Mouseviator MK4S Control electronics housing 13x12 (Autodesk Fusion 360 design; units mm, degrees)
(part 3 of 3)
sketch "Sketch2" plane through (0, 0, 5) normal (0, 0, 1) x axis (-1, 0, 0)
  line L1 (-60.9644, -51.9879) -> (-20.9644, -51.9879)
  line L2 (-55.9644, -54.9879) -> (-60.9644, -51.9879)
  line L3 (-85.9644, -54.9879) -> (-55.9644, -54.9879)
  line L4 (-80.9644, -51.9879) -> (-85.9644, -54.9879)
  line L5 (-120.9644, -51.9879) -> (-80.9644, -51.9879)
  line L6 (-120.9644, -6.9879) -> (-120.9644, -51.9879)
  line L7 (-123.9644, -11.9879) -> (-120.9644, -6.9879)
  line L8 (-123.9644, 18.0121) -> (-123.9644, -11.9879)
  line L9 (-120.9644, 13.0121) -> (-123.9644, 18.0121)
  line L10 (-120.9644, 58.0121) -> (-120.9644, 13.0121)
  line L11 (-80.9644, 58.0121) -> (-120.9644, 58.0121)
  line L12 (-85.9644, 61.0121) -> (-80.9644, 58.0121)
  line L13 (-55.9644, 61.0121) -> (-85.9644, 61.0121)
  line L14 (-60.9644, 58.0121) -> (-55.9644, 61.0121)
  line L15 (-20.9644, 58.0121) -> (-60.9644, 58.0121)
  line L16 (-20.9644, 13.0121) -> (-20.9644, 58.0121)
  line L17 (-17.9644, 18.0121) -> (-20.9644, 13.0121)
  line L18 (-17.9644, -11.9879) -> (-17.9644, 18.0121)
  line L19 (-20.9644, -6.9879) -> (-17.9644, -11.9879)
  line L20 (-20.9644, -51.9879) -> (-20.9644, -6.9879)
  line L21 (-128.9644, 60.0121) -> (-122.9644, 60.0121)
  line L22 (-128.9644, 66.0121) -> (-128.9644, 60.0121)
  line L23 (-122.9644, 66.0121) -> (-128.9644, 66.0121)
  line L24 (-122.9644, 60.0121) -> (-122.9644, 66.0121)
  line L25 (-128.9644, -53.9879) -> (-128.9644, -59.9879)
  line L26 (-122.9644, -53.9879) -> (-128.9644, -53.9879)
  line L27 (-122.9644, -59.9879) -> (-122.9644, -53.9879)
  line L28 (-128.9644, -59.9879) -> (-122.9644, -59.9879)
  line L29 (-12.9644, -53.9879) -> (-18.9644, -53.9879)
  line L30 (-12.9644, -59.9879) -> (-12.9644, -53.9879)
  line L31 (-18.9644, -59.9879) -> (-12.9644, -59.9879)
  line L32 (-18.9644, -53.9879) -> (-18.9644, -59.9879)
  line L33 (-12.9644, 60.0121) -> (-12.9644, 66.0121)
  line L34 (-18.9644, 60.0121) -> (-12.9644, 60.0121)
  line L35 (-18.9644, 66.0121) -> (-18.9644, 60.0121)
  line L36 (-12.9644, 66.0121) -> (-18.9644, 66.0121)
  line L37 (-10.9644, -6.9879) -> (-10.9644, -61.9879)
  line L38 (-13.9644, -11.9879) -> (-10.9644, -6.9879)
  line L39 (-13.9644, 18.0121) -> (-13.9644, -11.9879)
  line L40 (-10.9644, 13.0121) -> (-13.9644, 18.0121)
  line L41 (-10.9644, 68.0121) -> (-10.9644, 13.0121)
  line L42 (-60.9644, 68.0121) -> (-10.9644, 68.0121)
  line L43 (-55.9644, 65.0121) -> (-60.9644, 68.0121)
  line L44 (-85.9644, 65.0121) -> (-55.9644, 65.0121)
  line L45 (-80.9644, 68.0121) -> (-85.9644, 65.0121)
  line L46 (-130.9644, 68.0121) -> (-80.9644, 68.0121)
  line L47 (-130.9644, 13.0121) -> (-130.9644, 68.0121)
  line L48 (-127.9644, 18.0121) -> (-130.9644, 13.0121)
  line L49 (-127.9644, -11.9879) -> (-127.9644, 18.0121)
  line L50 (-130.9644, -6.9879) -> (-127.9644, -11.9879)
  line L51 (-130.9644, -61.9879) -> (-130.9644, -6.9879)
  line L52 (-80.9644, -61.9879) -> (-130.9644, -61.9879)
  line L53 (-85.9644, -58.9879) -> (-80.9644, -61.9879)
  line L54 (-55.9644, -58.9879) -> (-85.9644, -58.9879)
  line L55 (-60.9644, -61.9879) -> (-55.9644, -58.9879)
  line L56 (-10.9644, -61.9879) -> (-60.9644, -61.9879)
  line L57 (-60.9644, -51.9879) -> (-20.9644, -51.9879)
  line L58 (-20.9644, -6.9879) -> (-20.9644, -51.9879)
  line L59 (-17.9644, -11.9879) -> (-17.9644, 3.0121)
  line L60 (-17.9644, 18.0121) -> (-17.9644, 3.0121)
  line L61 (-17.9644, 18.0121) -> (-20.9644, 13.0121)
  line L62 (-17.9644, -11.9879) -> (-20.9644, -6.9879)
  line L63 (-20.9644, 13.0121) -> (-20.9644, 58.0121)
  line L64 (-60.9644, 58.0121) -> (-20.9644, 58.0121)
  line L65 (-55.9644, 61.0121) -> (-70.9644, 61.0121)
  line L66 (-85.9644, 61.0121) -> (-70.9644, 61.0121)
  line L67 (-80.9644, 58.0121) -> (-85.9644, 61.0121)
  line L68 (-55.9644, 61.0121) -> (-60.9644, 58.0121)
  line L69 (-80.9644, 58.0121) -> (-120.9644, 58.0121)
  line L70 (-120.9644, 58.0121) -> (-120.9644, 13.0121)
  line L71 (-123.9644, 18.0121) -> (-123.9644, 3.0121)
  line L72 (-123.9644, 18.0121) -> (-120.9644, 13.0121)
  line L73 (-123.9644, -11.9879) -> (-123.9644, 3.0121)
  line L74 (-123.9644, -11.9879) -> (-120.9644, -6.9879)
  line L75 (-120.9644, -6.9879) -> (-120.9644, -51.9879)
  line L76 (-80.9644, -51.9879) -> (-120.9644, -51.9879)
  line L77 (-85.9644, -54.9879) -> (-70.9644, -54.9879)
  line L78 (-80.9644, -51.9879) -> (-85.9644, -54.9879)
  line L79 (-55.9644, -54.9879) -> (-60.9644, -51.9879)
  line L80 (-55.9644, -54.9879) -> (-70.9644, -54.9879)
  line L81 (-110.9144, -41.9379) -> (-31.0144, -41.9379)
  line L82 (-110.9144, 47.9621) -> (-110.9144, -41.9379)
  line L83 (-31.0144, 47.9621) -> (-110.9144, 47.9621)
  line L84 (-31.0144, -41.9379) -> (-31.0144, 47.9621)
  line L85 (-120.9144, -51.9379) -> (-80.7839, -51.9379)
  line L86 (-120.9144, -6.8074) -> (-120.9144, -51.9379)
  line L87 (-123.9144, -11.8074) -> (-120.9144, -6.8074)
  line L88 (-123.9144, 17.8316) -> (-123.9144, -11.8074)
  line L89 (-120.9144, 12.8316) -> (-123.9144, 17.8316)
  line L90 (-120.9144, 57.9621) -> (-120.9144, 12.8316)
  line L91 (-80.7839, 57.9621) -> (-120.9144, 57.9621)
  line L92 (-85.7839, 60.9621) -> (-80.7839, 57.9621)
  line L93 (-56.1449, 60.9621) -> (-85.7839, 60.9621)
  line L94 (-61.1449, 57.9621) -> (-56.1449, 60.9621)
  line L95 (-21.0144, 57.9621) -> (-61.1449, 57.9621)
  line L96 (-21.0144, 12.8316) -> (-21.0144, 57.9621)
  line L97 (-18.0144, 17.8316) -> (-21.0144, 12.8316)
  line L98 (-18.0144, -11.8074) -> (-18.0144, 17.8316)
  line L99 (-21.0144, -6.8074) -> (-18.0144, -11.8074)
  line L100 (-21.0144, -51.9379) -> (-21.0144, -6.8074)
  line L101 (-61.1449, -51.9379) -> (-21.0144, -51.9379)
  line L102 (-56.1449, -54.9379) -> (-61.1449, -51.9379)
  line L103 (-85.7839, -54.9379) -> (-56.1449, -54.9379)
  line L104 (-80.7839, -51.9379) -> (-85.7839, -54.9379)
  line L105 (-80.7839, 57.9621) -> (-61.1449, 57.9621)
  line L106 (-120.9144, 12.8316) -> (-120.9144, -6.8074)
  line L107 (-80.7839, -51.9379) -> (-61.1449, -51.9379)
  line L108 (-21.0144, 12.8316) -> (-21.0144, -6.8074)
  line L109 (-21.0144, -51.9379) -> (-120.9644, 58.0121)
  line L110 (-120.9644, -51.9879) -> (-20.9644, 58.0121)
  line L111 (-27.7672, 57.9621) -> (-27.7217, 58.0121)
  line L112 (-21.0144, 50.5241) -> (-20.9644, 50.5791)
  line L113 (-110.9144, -33.4999) -> (-36.8581, 47.9621)
  line L114 (-120.9644, -44.5549) -> (-120.9144, -44.4999)
  line L115 (-105.0708, -41.9379) -> (-31.0144, 39.5241)
  line L116 (-114.2071, -51.9879) -> (-114.1617, -51.9379)
  line L117 (-114.1618, 57.9621) -> (-114.2073, 58.0121)
  line L118 (-120.9144, 50.5239) -> (-120.9644, 50.5789)
  line L119 (-31.0144, -33.5042) -> (-105.0713, 47.9621)
  line L120 (-36.8621, -41.9379) -> (-110.9144, 39.5234)
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  point P79 (-120.9644, 58.0121)
  point P130 (-120.9644, 58.0121)
  point P73 (-20.9644, 58.0121)
  point P131 (-20.9644, 58.0121)
  point P85 (-120.9644, -51.9879)
  point P132 (-120.9644, -51.9879)
  point P133 (-27.7217, 58.0121)
  point P134 (-27.7672, 57.9621)
  point P135 (-36.8581, 47.9621)
  point P136 (-20.9644, 50.5791)
  point P137 (-21.0144, 50.5241)
  point P138 (-31.0144, 39.5241)
  point P139 (-110.9144, -33.4999)
  point P140 (-120.9144, -44.4999)
  point P141 (-120.9644, -44.5549)
  point P142 (-105.0708, -41.9379)
  point P143 (-114.1617, -51.9379)
  point P144 (-114.2071, -51.9879)
  point P145 (-114.2073, 58.0121)
  point P146 (-114.1618, 57.9621)
  point P147 (-105.0713, 47.9621)
  point P148 (-120.9644, 50.5789)
  point P149 (-120.9144, 50.5239)
  point P150 (-110.9144, 39.5234)
  point P151 (-31.0144, -33.5042)
  point P152 (-21.0144, -44.5047)
  point P153 (-36.8621, -41.9379)
  point P154 (-27.7716, -51.9379)
  point P155 (-20.9644, -44.5597)
  point P156 (-27.7261, -51.9879)
  horizontal L81
  vertical L82
  horizontal L83
  vertical L84
  coincident P79 P130
  coincident P73 P131
  coincident P85 P132
  coincident L15 P133
  coincident L95 P134
  coincident L83 P135
  collinear L111 L113
  coincident L16 P136
  coincident L96 P137
  coincident L84 P138
  collinear L112 L115
  coincident L82 P139
  coincident L86 P140
  collinear L113 L114
  coincident L6 P141
  coincident L81 P142
  coincident L85 P143
  collinear L115 L116
  coincident L5 P144
  coincident L11 P145
  coincident L91 P146
  coincident L83 P147
  collinear L117 L119
  coincident L10 P148
  coincident L90 P149
  coincident L82 P150
  collinear L118 L120
  coincident L84 P151
  coincident L100 P152
  coincident L81 P153
  coincident L101 P154
  coincident L20 P155
  coincident L1 P156
  dimension "d293" = 0.05 (= "wall_clearance")
  dimension "d294" distance L81 L85 = 10 (= "plate_square_thick")
  dimension "d295" distance L82 L86 = 10 (= "plate_square_thick")
  dimension "d296" distance L84 L100 = 10 (= "plate_square_thick")
  dimension "d297" distance L83 L91 = 10 (= "plate_square_thick")
extrude "Extrude1" new body sketch "Sketch2" along normal blind 5 (= "plate_thick")
extrude "Extrude2" add sketch "Sketch2" blind -2.45 (= "-( ( plate_thick / 2 ) - wall_clearance )") from offset 5 (= "plate_thick")
sketch "Sketch3" plane through (0, 0, 10) normal (0, 0, 1) x axis (-1, 0, 0)
  line L1 (-110.9144, 39.5234) -> (-110.9144, -33.4999)
  line L2 (-77.7228, 3.0109) -> (-110.9144, 39.5234)
  line L3 (-110.9144, -33.4999) -> (-77.7228, 3.0109)
  line L4 (-36.8581, 47.9621) -> (-105.0713, 47.9621)
  line L5 (-70.9655, 10.444) -> (-36.8581, 47.9621)
  line L6 (-105.0713, 47.9621) -> (-70.9655, 10.444)
  line L7 (-36.8621, -41.9379) -> (-70.9657, -4.4223)
  line L8 (-105.0708, -41.9379) -> (-36.8621, -41.9379)
  line L9 (-70.9657, -4.4223) -> (-105.0708, -41.9379)
  line L10 (-31.0144, 39.5241) -> (-64.2083, 3.0108)
  line L11 (-31.0144, -33.5042) -> (-31.0144, 39.5241)
  line L12 (-64.2083, 3.0108) -> (-31.0144, -33.5042)
  line L13 (-21.0144, -6.8074) -> (-21.0144, -51.9379)
  line L14 (-18.0144, -11.8074) -> (-21.0144, -6.8074)
  line L15 (-18.0144, 17.8316) -> (-18.0144, -11.8074)
  line L16 (-21.0144, 12.8316) -> (-18.0144, 17.8316)
  line L17 (-21.0144, 57.9621) -> (-21.0144, 12.8316)
  line L18 (-61.1449, 57.9621) -> (-21.0144, 57.9621)
  line L19 (-56.1449, 60.9621) -> (-61.1449, 57.9621)
  line L20 (-85.7839, 60.9621) -> (-56.1449, 60.9621)
  line L21 (-80.7839, 57.9621) -> (-85.7839, 60.9621)
  line L22 (-120.9144, 57.9621) -> (-80.7839, 57.9621)
  line L23 (-120.9144, 12.8316) -> (-120.9144, 57.9621)
  line L24 (-123.9144, 17.8316) -> (-120.9144, 12.8316)
  line L25 (-123.9144, -11.8074) -> (-123.9144, 17.8316)
  line L26 (-120.9144, -6.8074) -> (-123.9144, -11.8074)
  line L27 (-120.9144, -51.9379) -> (-120.9144, -6.8074)
  line L28 (-80.7839, -51.9379) -> (-120.9144, -51.9379)
  line L29 (-85.7839, -54.9379) -> (-80.7839, -51.9379)
  line L30 (-56.1449, -54.9379) -> (-85.7839, -54.9379)
  line L31 (-61.1449, -51.9379) -> (-56.1449, -54.9379)
  line L32 (-21.0144, -51.9379) -> (-61.1449, -51.9379)
  line L33 (-35.4144, -48.9379) -> (-117.9144, -48.9379)
  line L34 (-35.4144, 50.0621) -> (-35.4144, -48.9379)
  line L35 (-117.9144, 50.0621) -> (-35.4144, 50.0621)
  line L36 (-117.9144, -48.9379) -> (-117.9144, 50.0621)
  line L37 (-120.9144, -51.9379) -> (-80.7839, -51.9379)
  line L38 (-120.9144, -6.8074) -> (-120.9144, -51.9379)
  circle C1 centre (-111.4144, -47.2379) radius 1.7
  circle C2 centre (-40.9144, 45.5621) radius 1.7
  circle C3 centre (-111.4144, -47.2379) radius 4.25
  circle C4 centre (-40.9144, 45.5621) radius 4.25
  circle C5 centre (-40.9144, -48.0879) radius 4.25
  circle C6 centre (-111.4144, 46.0621) radius 4.25
  point P34 (-117.9144, -48.9379)
  point P35 (-35.4144, -48.9379)
  point P37 (-117.9144, 50.0621)
  point P41 (-111.4144, -47.2379)
  point P42 (-40.9144, 45.5621)
  point P45 (-40.9144, -48.0879)
  point P46 (-111.4144, 46.0621)
  horizontal L33
  vertical L34
  horizontal L35
  vertical L36
  concentric C1 C3
  concentric C2 C4
  dimension "d309" distance P34 P35 = 82.5 (= "psu_height")
  dimension "d310" distance P34 P37 = 99 (= "psu_width")
  dimension "d311" distance L33 L37 = 3
  dimension "d312" distance L36 L38 = 3
  dimension "d313" diameter C1 = 3.4 (= "M3_d")
  dimension "d314" distance L36 P41 = 6.5
  dimension "d315" distance L33 P41 = 1.7 (= "M3_d * 0.5")
  dimension "d316" diameter C2 = 3.4 (= "M3_d")
  dimension "d317" distance L34 P42 = 5.5
  dimension "d318" distance L35 P42 = 4.5
  dimension "d319" diameter C3 = 8.5 (= "M3_d * 2.5")
  dimension "d320" diameter C4 = 8.5 (= "M3_d * 2.5")
  dimension "d324" diameter C5 = 8.5 (= "M3_d * 2.5")
  dimension "d325" distance L33 P45 = 0.85 (= "M3_d * 0.25")
  dimension "d326" distance L34 P45 = 5.5
  dimension "d327" diameter C6 = 8.5 (= "M3_d * 2.5")
  dimension "d328" distance L36 P46 = 6.5
  dimension "d329" distance L35 P46 = 4
extrude "Extrude3" add sketch "Sketch3" profile of L4 L5 L28 L32 L37 C1 C2 C3 C4 C5 C6 along normal blind 5 (= "psu_stand_height")
extrude "Extrude4" add sketch "Sketch3" profile of L4 L5 C2 C4 no distance stored
fillet "Fillet1" radius 1.75 (= "psu_stand_height * 0.35")
sketch "Sketch4" plane through (0, 0, 15) normal (0, 0, 1) x axis (-1, 0, 0)
  circle C1 centre (-40.9144, -48.0879) radius 4.25
  circle C2 centre (-111.4144, -47.2379) radius 1.7
  circle C3 centre (-40.9144, 45.5621) radius 1.7
hole "Hole1" HoleDepth 7.5 (= "psu_stand_height + ( plate_thick * 0.5 )") HoleDiameter 3.4 TipAngle 180
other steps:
base_feature "Base Feature" bodies "Base plate 13x12 insert - PSU holder"
derived_base_feature "Derived Base Feature1"
derived_base_feature "Derived Base Feature1" bodies "side cover"
create_component "CreateComponent1"
create_component "CreateComponent2"
create_component "CreateComponent4"
create_component "CreateComponent5"
create_component "CreateComponent6"
create_component "CreateComponent8"
joint_origin "JointOrigin3"
joint_origin "JointOrigin3"
joint_origin "JointOrigin4"
joint_origin "JointOrigin4"
joint_origin "JointOrigin5"
joint_origin "JointOrigin5"
joint_origin "JointOrigin6"
joint_origin "JointOrigin6"
create_component "CreateComponent10"
create_component "CreateComponent11"
create_component "CreateComponent15"
create_component "CreateComponent17"
create_component "CreateComponent18"
create_component "CreateComponent19"
create_component "CreateComponent20"
create_component "CreateComponent22"
create_component "CreateComponent23"
create_component "CreateComponent25"
create_component "CreateComponent26"
create_component "CreateComponent27"
reparent_decal "ReparentDecal1"
remove_body "RemoveBody1"
named bodies: "side cover", "Base plate 13x12 insert - PSU holder"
